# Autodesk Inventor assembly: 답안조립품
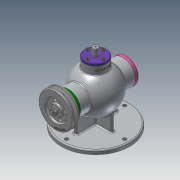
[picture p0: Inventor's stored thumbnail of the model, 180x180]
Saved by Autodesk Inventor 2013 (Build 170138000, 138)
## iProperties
Created: 2020-08
Part Number: 답안조립품
Document SubType Name: Assembly
Designer: CADCOM
Author: CADCOM
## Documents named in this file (18)
- C:\Users\CADCOM\Desktop\700806V1008\답안조립품.iam
- C:\Users\CADCOM\Desktop\700806V1008\본체.ipt
- C:\Users\CADCOM\Desktop\700806V1008\V-벨트풀리.ipt
- C:\Users\CADCOM\Desktop\700806V1008\너트 M8.ipt
- C:\Users\CADCOM\Desktop\700806V1008\뒤커버.ipt
- C:\Users\CADCOM\Desktop\700806V1008\멈춤링 15x1.ipt
- C:\Users\CADCOM\Desktop\700806V1008\멈춤링 35x1.6.ipt
- 멈춤링 35x1.6.ipt
- C:\Users\CADCOM\Desktop\700806V1008\베어링 6202.ipt
- 베어링 6202.ipt
- C:\Users\CADCOM\Desktop\700806V1008\볼트 M4.ipt
- C:\Users\CADCOM\Desktop\700806V1008\상부커버.ipt
- C:\Users\CADCOM\Desktop\700806V1008\슬라이드.ipt
- C:\Users\CADCOM\Desktop\700806V1008\앞커버.ipt
- C:\Users\CADCOM\Desktop\700806V1008\오일 실 15 30 7.ipt
- C:\Users\CADCOM\Desktop\700806V1008\칼라.ipt
- C:\Users\CADCOM\Desktop\700806V1008\키 3x3x12.ipt
- C:\Users\CADCOM\Desktop\700806V1008\편심축.ipt
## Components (1 placed, 1 different names)
1. V-벨트풀리:1
